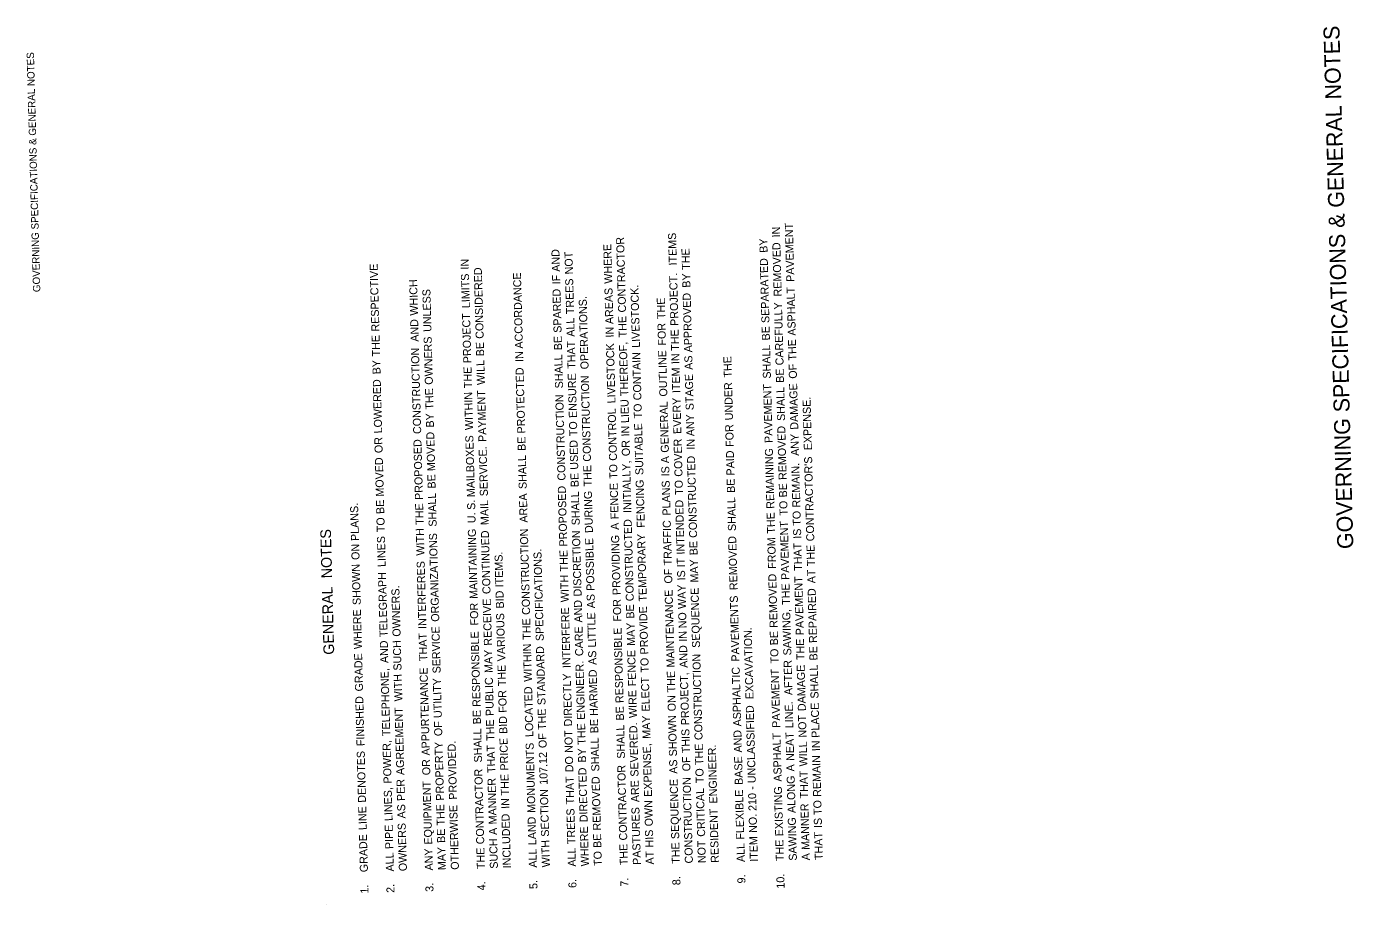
# Model space of a CAD drawing. Extents: x 1929542 to 1931706, y 595440 to 597808.
# Drawn here: x 1930711 to 1931706, y 597150 to 597808 of the extents above; entities that cross this region are included whole.
import ezdxf

# ---------------------------------------------------------------- set-up
doc = ezdxf.new("R2010")
doc.units = 0
for name, color, linetype in [('Default', 7, 'Continuous'), ('R_Annotation', 7, 'Continuous'), ('R_Border', 7, 'Continuous')]:
    doc.layers.add(name, color=color, linetype=linetype)

msp = doc.modelspace()

# ---------------------------------------------------------------- linework, layer by layer
at = {"layer": 'Default'}
msp.add_line((1930935.94, 597150.28), (1930935.94, 597150.28), dxfattribs=at)

# ---------------------------------------------------------------- texts
for s, height, p in [('  ITEMS', 6, (1931198.52, 597624.78)), (' IN', 6, (1931275.92, 597648.01)), (' PAVEMENT', 6, (1931286.57, 597614.7)), (' WHERE', 6, (1931150.06, 597613.31)), (' CONTRACTOR', 6, (1931160.39, 597591.76)), (' BY', 6, (1931266.48, 597636.52)), (' REMOVED', 6, (1931277.11, 597603.75)), (' IN', 6, (1931042.48, 597623.91)), (' AND', 6, (1931110.8, 597622.27)), (' NOT', 6, (1931120.61, 597620.31)), (' THE', 6, (1931208.3, 597623.77)), (' SEPARATED', 6, (1931267.89, 597583.87)), (' RESPECTIVE', 6, (1930975.45, 597577.49)), (' CONSIDERED', 6, (1931053.63, 597572.04)), (' ACCORDANCE', 6, (1931083.09, 597564.68)), (' WHICH', 6, (1931004.39, 597589.41)), (' LIMITS', 6, (1931043.26, 597595.02)), (' IF', 6, (1931111.05, 597612.88)), (' TREES', 6, (1931121.41, 597590.47)), (' LIVESTOCK.', 6, (1931170.85, 597565.31)), (' PROJECT.', 6, (1931199.67, 597581.74)), (' BY', 6, (1931208.66, 597610.32)), (' UNLESS', 6, (1931014.48, 597577.19)), (' SPARED', 6, (1931112.03, 597576.53)), (' OPERATIONS.', 6, (1931132.27, 597549.14)), (' AREAS', 6, (1931150.87, 597583.01)), (' THE', 6, (1931189.78, 597586.86)), (' APPROVED', 6, (1931209.96, 597561.86)), (' ASPHALT', 6, (1931287.65, 597574.35)), (' CAREFULLY', 6, (1931278.49, 597552.12)), (' AND', 6, (1931004.92, 597569.83)), (' PROJECT', 6, (1931044.37, 597553.74)), (' ALL', 6, (1931121.86, 597573.54)), (' THE', 6, (1931160.89, 597573.12)), (' FOR', 6, (1931190.31, 597566.96)), (' THE', 6, (1930975.95, 597558.85)), (' OWNERS', 6, (1931015.54, 597537.59)), (' BE', 6, (1931112.38, 597563.47)), (' IN', 6, (1931151.14, 597572.99)), (' THE', 6, (1931200.17, 597563.1)), (' BE', 6, (1931268.24, 597570.81)), (' CONSTRUCTION', 6, (1931006.78, 597500.68)), (' BE', 6, (1931053.98, 597558.98)), (' IN', 6, (1931083.36, 597554.66)), (' THAT', 6, (1931122.51, 597549.5)), (' LIVESTOCK', 6, (1931152.46, 597523.64)), (' THEREOF,', 6, (1931162.07, 597529.16)), (' OUTLINE', 6, (1931191.34, 597528.76)), (' SHALL', 6, (1931269.01, 597542.22)), (' THE', 6, (1931288.15, 597555.7)), (' BY', 6, (1930976.32, 597545.41)), (' WILL', 6, (1931054.56, 597537.4)), (' SHALL', 6, (1931113.15, 597534.89)), (' CONTAIN', 6, (1931171.91, 597525.95)), (' IN', 6, (1931200.44, 597553.08)), (' AS', 6, (1931210.31, 597548.79)), (' THE', 6, (1931239.73, 597542.95)), (' OF', 6, (1931288.52, 597542.12)), (' THE', 6, (1931044.87, 597535.1)), (' PROTECTED', 6, (1931084.79, 597501.09)), (' ENSURE', 6, (1931123.5, 597512.69)), (' CONSTRUCTION', 6, (1931134.13, 597479.98)), (' ITEM', 6, (1931201.02, 597531.36)), (' STAGE', 6, (1931211.12, 597518.5)), (' BE', 6, (1931278.84, 597539.06)), (' LOWERED', 6, (1930977.5, 597501.15)), (' THE', 6, (1931016.04, 597518.95)), (' PAYMENT', 6, (1931055.7, 597494.73)), (' UNDER', 6, (1931240.59, 597510.94)), (' PAVEMENT', 6, (1931270.3, 597493.96)), (' SHALL', 6, (1931279.61, 597510.48)), (' DAMAGE', 6, (1931289.54, 597503.92)), (' WITHIN', 6, (1931045.71, 597503.67)), (' CONSTRUCTION', 6, (1931115, 597465.74)), (' LIEU', 6, (1931162.61, 597508.88)), (' TO', 6, (1931172.27, 597512.36)), (' GENERAL', 6, (1931192.47, 597486.67)), (' EVERY', 6, (1931201.85, 597500.68)), (' EXPENSE.', 6, (1931299.71, 597488.5)), (' BY', 6, (1931016.4, 597505.5)), (' CONTROL', 6, (1931153.62, 597480.63)), (' ANY', 6, (1931211.65, 597499)), (' MOVED', 6, (1931017.28, 597472.89)), (' TO', 6, (1931123.86, 597499.09)), (' IN', 6, (1931162.88, 597498.86)), (' SUITABLE', 6, (1931173.41, 597469.96)), (' FOR', 6, (1931241.12, 597491.03)), (' REMOVED', 6, (1931280.8, 597466.22)), (' OR', 6, (1930977.9, 597486.37)), (' PROPOSED', 6, (1931008.1, 597451.29)), (' MAILBOXES', 6, (1931047.06, 597453.34)), (' BE', 6, (1931085.14, 597488.03)), (' USED', 6, (1931124.54, 597473.93)), (' OR', 6, (1931163.28, 597484.08)), (' COVER', 6, (1931202.71, 597468.67)), (' IN', 6, (1931211.91, 597488.98)), ('  ANY', 6, (1931290.13, 597482.09)), (' MOVED', 6, (1930978.78, 597453.76)), (' SERVICE.', 6, (1931056.8, 597454.01)), (' SHALL', 6, (1931085.91, 597459.45)), (' A', 6, (1931192.68, 597478.74)), (' CONSTRUCTED', 6, (1931213.69, 597422.85)), (' PAID', 6, (1931241.7, 597469.59)), (' REMAINING', 6, (1931271.63, 597444.66)), (" CONTRACTOR'S", 6, (1931301.54, 597420.29)), (' THE', 6, (1931134.63, 597461.34)), (' TO', 6, (1931153.98, 597467.04)), (' INITIALLY,', 6, (1931164.42, 597441.52)), (' IS', 6, (1931192.95, 597468.93)), (' REMAIN.', 6, (1931291.11, 597445.58)), (' BE', 6, (1931017.63, 597459.83)), (' BE', 6, (1931124.89, 597460.87)), (' FENCE', 6, (1931154.8, 597436.76)), (' FENCING', 6, (1931174.47, 597430.44)), (' PLANS', 6, (1931193.73, 597439.56)), (' TO', 6, (1931203.07, 597455.07)), (' BE', 6, (1931242.05, 597456.53)), (' BE', 6, (1931281.15, 597453.16)), (' SHALL', 6, (1931018.39, 597431.25)), (' AREA', 6, (1931086.59, 597434.28)), (' PROPOSED', 6, (1931116.33, 597416.35)), (' SHALL', 6, (1931125.65, 597432.29)), (' DURING', 6, (1931135.56, 597426.48)), (' SHALL', 6, (1931242.81, 597427.95)), (' PLANS.', 6, (1930960.16, 597420.52)), (' BE', 6, (1930979.13, 597440.7)), (' THE', 6, (1931008.6, 597432.65)), (' S.', 6, (1931047.32, 597443.83)), (' MAIL', 6, (1931057.38, 597432.42)), (' INTENDED', 6, (1931204.27, 597410.36)), (' TO', 6, (1931281.52, 597439.57)), (' TO', 6, (1931291.47, 597431.98)), (' TO', 6, (1930979.49, 597427.1)), (' U.', 6, (1931047.58, 597433.86)), (' A', 6, (1931155.01, 597428.82)), (' CONSTRUCTED', 6, (1931166.2, 597375.38)), (' TRAFFIC', 6, (1931194.74, 597402.19)), (' THE', 6, (1931272.13, 597426.02)), (' PAVEMENT', 6, (1931282.81, 597391.31)), (' NOTES', 8, (1930940.04, 597391.84)), (' LINES', 6, (1930980.19, 597401)), (' WITH', 6, (1931009.22, 597409.59)), (' ORGANIZATIONS', 6, (1931020.31, 597359.98)), (' MAINTAINING', 6, (1931049.11, 597377.11)), (' CONTINUED', 6, (1931058.76, 597380.72)), (' CONSTRUCTION', 6, (1931088.44, 597365.13)), (' DISCRETION', 6, (1931127.09, 597378.96)), (' POSSIBLE', 6, (1931136.73, 597383.14)), (' PROVIDING', 6, (1931156.32, 597379.99)), (' TEMPORARY', 6, (1931175.96, 597375.09)), (' REMOVED', 6, (1931244, 597383.69)), (' FROM', 6, (1931272.83, 597399.65)), (' IS', 6, (1931291.74, 597422.18)), (' ON', 6, (1930960.54, 597406.31)), (' SPECIFICATIONS.', 6, (1931098.72, 597345.52)), (' THE', 6, (1931116.83, 597397.71)), (' BE', 6, (1931214.04, 597409.79)), (' THAT', 6, (1931292.38, 597398.14)), (' THE', 6, (1931302.04, 597401.64)), (' SHOWN', 6, (1930961.45, 597372.54)), (' INTERFERES', 6, (1931010.7, 597354.61)), (' ITEMS.', 6, (1931068.38, 597385.8)), (' IT', 6, (1931204.53, 597400.75)), (' MAY', 6, (1931214.59, 597389.36)), (' TELEGRAPH', 6, (1930981.6, 597348.58)), (' WITH', 6, (1931117.45, 597374.65)), (' OF', 6, (1931195.1, 597388.6)), (' IS', 6, (1931204.79, 597390.95)), (' REMOVED', 6, (1931274.02, 597355.4)), (' PAVEMENT', 6, (1931293.68, 597349.87)), (' AT', 6, (1931302.39, 597388.78)), ('GENERAL', 8, (1930941.5, 597337.53)), (' OWNERS.', 6, (1930991.35, 597348.8)), (' BID', 6, (1931068.81, 597369.95)), (' MAINTENANCE', 6, (1931196.79, 597325.72)), (' WAY', 6, (1931205.37, 597369.59)), (' SEQUENCE', 6, (1931215.9, 597340.44)), (' THE', 6, (1931283.31, 597372.66)), (' REPAIRED', 6, (1931303.59, 597344.05)), (' FOR', 6, (1931049.64, 597357.21)), (' RECEIVE', 6, (1931059.8, 597342.05)), (' AND', 6, (1931127.61, 597359.38)), (' AS', 6, (1931137.08, 597370.07)), (' FOR', 6, (1931156.85, 597360.09)), (' BE', 6, (1931166.55, 597362.32)), (' PAVEMENTS', 6, (1931245.44, 597330.11)), (' WHERE', 6, (1930962.34, 597339.47)), (' VARIOUS', 6, (1931069.87, 597330.34)), (' INTERFERE', 6, (1931118.77, 597325.27)), (' LITTLE', 6, (1931137.87, 597340.72)), (' PROVIDE', 6, (1931177.02, 597335.49)), (' NO', 6, (1931205.76, 597355.07)), (' SAWING,', 6, (1931284.33, 597334.77)), (' SERVICE', 6, (1931021.35, 597321.3)), (' THE', 6, (1931088.94, 597346.48)), (' CARE', 6, (1931128.29, 597334.22)), (' RESPONSIBLE', 6, (1931158.49, 597299.05)), (' MAY', 6, (1931167.1, 597341.89)), (' EXCAVATION.', 6, (1931255.95, 597301.89)), (' BE', 6, (1931274.37, 597342.33)), (' AND', 6, (1930982.12, 597329)), (' SUCH', 6, (1930992.03, 597323.4)), (' THAT', 6, (1931011.34, 597330.57)), (' RESPONSIBLE', 6, (1931051.28, 597296.17)), (' WITHIN', 6, (1931089.79, 597315.05)), (' IN', 6, (1931206.02, 597345.05)), (' THE', 6, (1931294.18, 597331.23)), (' GRADE', 6, (1930963.19, 597307.78)), (' MAY', 6, (1931060.35, 597321.62)), (' STANDARD', 6, (1931100.01, 597297.53)), (' AS', 6, (1931138.22, 597327.65)), (' FENCE', 6, (1931167.91, 597311.61)), (' AND', 6, (1931206.55, 597325.47)), (' CONSTRUCTION', 6, (1931217.76, 597271.29)), (' TO', 6, (1931274.74, 597328.74)), (' BE', 6, (1931303.94, 597330.99)), (' TELEPHONE,', 6, (1930983.59, 597274.33)), (' APPURTENANCE', 6, (1931013.24, 597259.76)), (' THE', 6, (1931070.37, 597311.7)), (' ENGINEER.', 6, (1931129.57, 597286.52)), (' HARMED', 6, (1931139.24, 597289.45)), (' TO', 6, (1931177.39, 597321.9)), (' THE', 6, (1931197.29, 597307.08)), (' ASPHALTIC', 6, (1931246.74, 597281.54)), (' PAVEMENT', 6, (1931276.03, 597280.48)), ('  AFTER', 6, (1931285.19, 597302.75)), (' DAMAGE', 6, (1931295.2, 597293.02)), (' SHALL', 6, (1931304.7, 597302.41)), (' WITH', 6, (1930992.65, 597300.34)), (' UTILITY', 6, (1931022.24, 597287.84)), (' PUBLIC', 6, (1931061.22, 597289.35)), (' DIRECTLY', 6, (1931119.95, 597281.56)), (' ELECT', 6, (1931178.17, 597292.73)), (' PROJECT,', 6, (1931207.71, 597282.44)), (' FINISHED', 6, (1930964.29, 597266.79)), (' FOR', 6, (1931070.91, 597291.79)), (' LOCATED', 6, (1931090.9, 597273.59)), (' WIRE', 6, (1931168.55, 597287.85)), (' ON', 6, (1931197.67, 597292.87)), (' AGREEMENT', 6, (1930994.13, 597245.1)), (' BE', 6, (1931051.63, 597283.11)), (' THE', 6, (1931100.51, 597278.89)), (' BE', 6, (1931158.84, 597285.99)), (' UNCLASSIFIED', 6, (1931257.64, 597239)), (' LINE.', 6, (1931285.79, 597280.2)), (' PLACE', 6, (1931305.49, 597273.04)), (' OF', 6, (1931022.61, 597274.26)), (' THE', 6, (1931061.72, 597270.71)), (' BID', 6, (1931071.33, 597275.94)), (' THE', 6, (1931130.07, 597267.88)), (' BE', 6, (1931139.59, 597276.39)), (' SEVERED.', 6, (1931169.73, 597243.87)), (' MAY', 6, (1931178.72, 597272.3)), (' SHOWN', 6, (1931198.58, 597259.1)), (' NOT', 6, (1931295.74, 597273.17)), (' SHALL', 6, (1931052.4, 597254.53)), (' OF', 6, (1931100.88, 597265.31)), (' NOT', 6, (1931120.48, 597261.71)), (' SHALL', 6, (1931159.61, 597257.41)), (' THIS', 6, (1931208.27, 597261.47)), (' AND', 6, (1931247.27, 597261.96)), (' ASPHALT', 6, (1931277.12, 597240.12)), (' NEAT', 6, (1931286.45, 597255.69)), (' POWER,', 6, (1930984.55, 597238.76)), (' PROPERTY', 6, (1931023.91, 597225.89)), (' PROVIDED.', 6, (1931033.64, 597226.65)), (' THAT', 6, (1931062.36, 597246.67)), (' PRICE', 6, (1931072.07, 597248.45)), (' MONUMENTS', 6, (1931092.43, 597216.76)), (' BY', 6, (1931130.43, 597254.43)), (' SHALL', 6, (1931140.36, 597247.81)), (' EXPENSE,', 6, (1931179.88, 597228.79)), (' THE', 6, (1931218.26, 597252.64)), (' ENGINEER.', 6, (1931228.79, 597223.79)), (' WILL', 6, (1931296.32, 597251.59)), (' IN', 6, (1931305.76, 597263.02)), (' DENOTES', 6, (1930965.43, 597224.38)), (' OR', 6, (1931013.64, 597244.98)), (' 107.12', 6, (1931101.61, 597237.81)), (' DO', 6, (1931120.87, 597247.19)), (' AS', 6, (1931198.93, 597246.03)), (' OF', 6, (1931208.63, 597247.88)), (' BASE', 6, (1931247.92, 597237.72)), (' REMAIN', 6, (1931306.68, 597228.79)), (' CONTRACTOR', 6, (1931054.05, 597193.19)), (' THE', 6, (1931072.57, 597229.81)), (' THAT', 6, (1931121.52, 597223.15)), (' DIRECTED', 6, (1931131.63, 597209.71)), (' REMOVED', 6, (1931141.55, 597203.55)), (' CONTRACTOR', 6, (1931161.26, 597196.07)), (' TO', 6, (1931218.62, 597239.05)), (' A', 6, (1931286.66, 597247.76)), (' ALONG', 6, (1931287.5, 597216.61)), (' THAT', 6, (1931296.96, 597227.55)), (' LINES,', 6, (1930985.3, 597210.63)), (' PER', 6, (1930994.65, 597225.65)), (' EQUIPMENT', 6, (1931015.04, 597193)), (' MANNER', 6, (1931063.4, 597208.14)), (' SECTION', 6, (1931102.66, 597198.91)), (' ARE', 6, (1931170.24, 597224.75)), (' SEQUENCE', 6, (1931200.24, 597197.11)), ('CONSTRUCTION', 6, (1931210.43, 597181.06)), (' CRITICAL', 6, (1931219.7, 597198.84)), (' FLEXIBLE', 6, (1931249.02, 597196.71)), (' -', 6, (1931257.77, 597234.15)), (' EXISTING', 6, (1931278.21, 597199.2)), (' IN', 6, (1931072.84, 597219.79)), (' OWN', 6, (1931180.48, 597206.67)), (' 210', 6, (1931258.2, 597218.25)), (' MANNER', 6, (1931297.99, 597189.02)), (' TO', 6, (1931307.05, 597215.19)), (' LINE', 6, (1930965.98, 597203.88)), (' AS', 6, (1930995, 597212.58)), (' THE', 6, (1931024.41, 597207.25)), ('OTHERWISE', 6, (1931034.99, 597176.35)), ('INCLUDED', 6, (1931073.98, 597177.39)), (' LAND', 6, (1931093.08, 597192.53)), (' TREES', 6, (1931122.32, 597193.31)), ('PASTURES', 6, (1931171.44, 597180.01)), ('RESIDENT', 6, (1931229.92, 597181.58)), (' NO.', 6, (1931258.64, 597201.75)), (' PIPE', 6, (1930985.87, 597189.65)), ('OWNERS', 6, (1930996, 597175.3)), (' BE', 6, (1931024.76, 597194.19)), (' A', 6, (1931063.61, 597200.21)), ('WHERE', 6, (1931132.46, 597178.96)), (' HIS', 6, (1931180.9, 597190.81)), ('SAWING', 6, (1931288.4, 597183.15)), (' IS', 6, (1931307.31, 597205.39)), ('GRADE', 6, (1930966.76, 597174.52)), ('SUCH', 6, (1931064.23, 597177.13)), ('WITH', 6, (1931103.22, 597178.18)), (' BE', 6, (1931141.9, 597190.49)), ('THE', 6, (1931200.68, 597180.8)), ('NOT', 6, (1931220.17, 597181.32)), ('ALL', 6, (1931249.41, 597182.1)), ('ITEM', 6, (1931259.16, 597182.37)), ('THE', 6, (1931278.65, 597182.89)), ('THAT', 6, (1931307.89, 597183.67)), ('ALL', 6, (1930986.26, 597175.04)), ('ANY', 6, (1931015.5, 597175.82)), ('MAY', 6, (1931025.24, 597176.09)), ('THE', 6, (1931054.48, 597176.87)), ('ALL', 6, (1931093.47, 597177.92)), ('ALL', 6, (1931122.71, 597178.7)), ('TO', 6, (1931142.2, 597179.23)), ('THE', 6, (1931161.69, 597179.75)), ('AT', 6, (1931181.19, 597180.27)), ('A', 6, (1931298.15, 597183.41)), ('4.', 6, (1931054.91, 597160.87)), ('5.', 6, (1931093.9, 597161.92)), ('6.', 6, (1931123.14, 597162.7)), ('7.', 6, (1931162.12, 597163.75)), ('8.', 6, (1931201.11, 597164.8)), ('9.', 6, (1931249.84, 597166.1)), ('10.', 6, (1931279.21, 597162.23)), ('1.', 6, (1930967.19, 597158.52)), ('2.', 6, (1930986.69, 597159.04)), ('3.', 6, (1931015.93, 597159.82))]:
    msp.add_text(s, height=height, rotation=91.53769, dxfattribs=at).set_placement(p)
at = {"layer": 'R_Annotation'}
msp.add_text('GOVERNING SPECIFICATIONS & GENERAL NOTES', height=12, rotation=91.53769, dxfattribs=at).set_placement((1931705.66, 597416.78))
at = {"layer": 'R_Border'}
msp.add_text('GOVERNING SPECIFICATIONS & GENERAL NOTES', height=5.5, rotation=91.53769, dxfattribs=at).set_placement((1930721.15, 597609.23))

doc.saveas('drawing.dxf')
